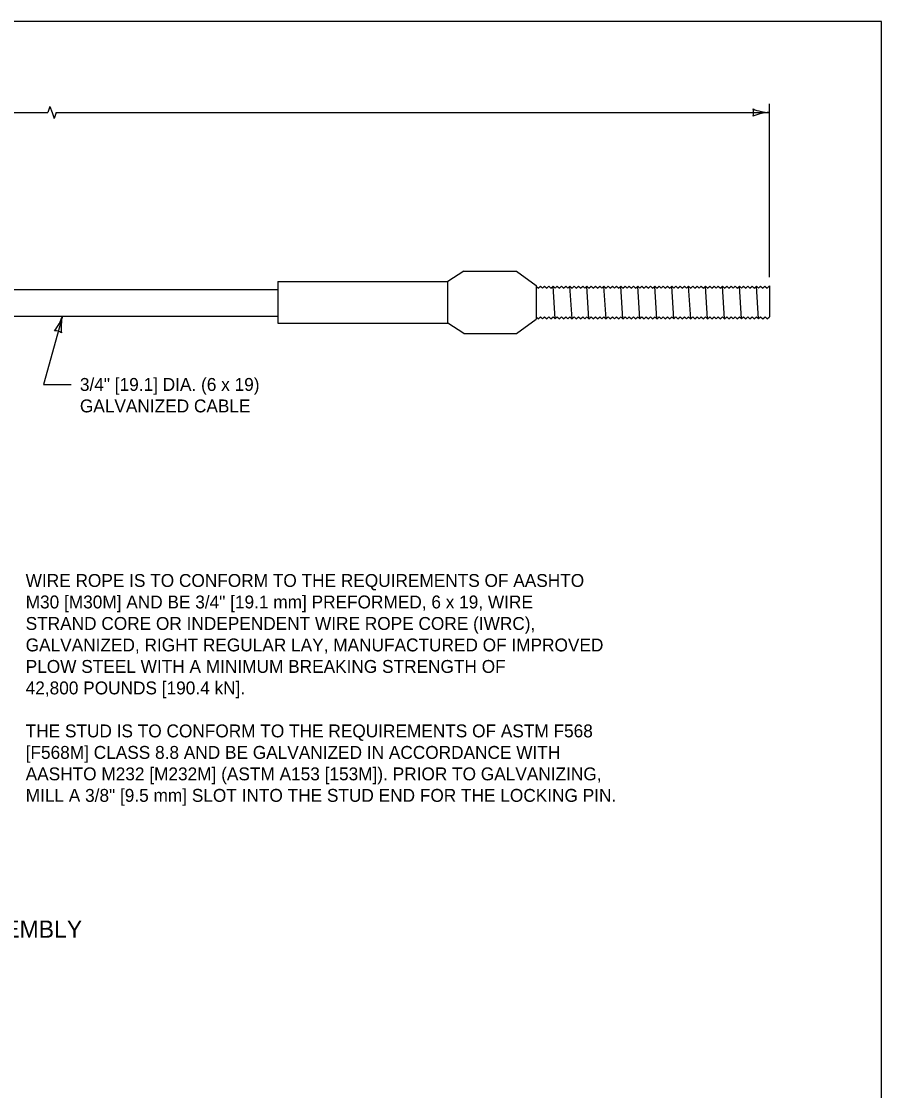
# Model space of a CAD drawing. Extents: x 49991.4 to 50021, y 49987.6 to 50011.4.
# Drawn here: x 50004.612 to 50008.615, y 50006.287 to 50011.263 of the extents above; entities that cross this region are included whole.
import ezdxf

# ---------------------------------------------------------------- set-up
doc = ezdxf.new("R2010")
doc.units = 0
for name, color, linetype in [('Level 1', 7, 'Continuous'), ('Level 2', 7, 'Continuous'), ('Level 3', 7, 'Continuous')]:
    doc.layers.add(name, color=color, linetype=linetype)

msp = doc.modelspace()

# ---------------------------------------------------------------- linework, layer by layer
at = {"layer": 'Level 1'}
for p, q in [((50006.6708, 50010.1011), (50006.5956, 50010.0531)), ((50006.6708, 50010.1011), (50006.9152, 50010.1011)), ((50006.9152, 50010.1011), (50007.007, 50010.0335)), ((50005.8048, 50010.0531), (50005.8048, 50009.8577)), ((50005.8048, 50010.0531), (50006.5956, 50010.0531)), ((50006.5956, 50009.8577), (50006.5956, 50010.0531)), ((50004.5624, 50010.0157), (50005.8048, 50010.0157)), ((50007.007, 50010.0335), (50007.007, 50009.8771)), ((50007.007, 50010.0311), (50007.017, 50010.0213)), ((50007.017, 50010.0213), (50007.0268, 50010.0311)), ((50007.0268, 50010.0311), (50007.0366, 50010.0213)), ((50007.0366, 50010.0213), (50007.0464, 50010.0311)), ((50007.0464, 50010.0311), (50007.0564, 50010.0213)), ((50007.0564, 50010.0213), (50007.0662, 50010.0311)), ((50007.0662, 50010.0311), (50007.076, 50010.0213)), ((50007.076, 50010.0213), (50007.0858, 50010.0311)), ((50007.0858, 50010.0311), (50007.0958, 50010.0213)), ((50007.0958, 50009.8785), (50007.0858, 50010.0311)), ((50007.0958, 50010.0213), (50007.1056, 50010.0311)), ((50007.1056, 50010.0311), (50007.1154, 50010.0213)), ((50007.1154, 50010.0213), (50007.1252, 50010.0311)), ((50007.1252, 50010.0311), (50007.135, 50010.0213)), ((50007.135, 50010.0213), (50007.145, 50010.0311)), ((50007.145, 50010.0311), (50007.1546, 50010.0213)), ((50007.1546, 50010.0213), (50007.1646, 50010.0311)), ((50007.1646, 50010.0311), (50007.1744, 50010.0213)), ((50007.1744, 50009.8785), (50007.1646, 50010.0311)), ((50007.1744, 50010.0213), (50007.1844, 50010.0311)), ((50007.1844, 50010.0311), (50007.194, 50010.0213)), ((50007.194, 50010.0213), (50007.2038, 50010.0311)), ((50007.2038, 50010.0311), (50007.2138, 50010.0213)), ((50007.2138, 50010.0213), (50007.2238, 50010.0311)), ((50007.2238, 50010.0311), (50007.2334, 50010.0213)), ((50007.2334, 50010.0213), (50007.2434, 50010.0311)), ((50007.2434, 50010.0311), (50007.253, 50010.0213)), ((50007.253, 50009.8785), (50007.2434, 50010.0311)), ((50007.253, 50010.0213), (50007.263, 50010.0311)), ((50007.263, 50010.0311), (50007.2732, 50010.0213)), ((50007.2732, 50010.0213), (50007.283, 50010.0311)), ((50007.283, 50010.0311), (50007.2928, 50010.0213)), ((50007.2928, 50010.0213), (50007.3028, 50010.0311)), ((50007.3028, 50010.0311), (50007.3126, 50010.0213)), ((50007.3126, 50010.0213), (50007.3224, 50010.0311)), ((50007.3224, 50010.0311), (50007.3322, 50010.0213)), ((50007.3322, 50009.8785), (50007.3224, 50010.0311)), ((50007.3322, 50010.0213), (50007.342, 50010.0311)), ((50007.342, 50010.0311), (50007.352, 50010.0213)), ((50007.352, 50010.0213), (50007.3618, 50010.0311)), ((50007.3618, 50010.0311), (50007.3716, 50010.0213)), ((50007.3716, 50010.0213), (50007.3814, 50010.0311)), ((50007.3814, 50010.0311), (50007.3914, 50010.0213)), ((50007.3914, 50010.0213), (50007.4012, 50010.0311)), ((50007.4012, 50010.0311), (50007.4108, 50010.0213)), ((50007.4108, 50009.8785), (50007.4012, 50010.0311)), ((50007.4108, 50010.0213), (50007.4208, 50010.0311)), ((50007.4208, 50010.0311), (50007.4308, 50010.0213)), ((50007.4308, 50010.0213), (50007.4406, 50010.0311)), ((50007.4406, 50010.0311), (50007.4504, 50010.0213)), ((50007.4504, 50010.0213), (50007.46, 50010.0311)), ((50007.46, 50010.0311), (50007.47, 50010.0213)), ((50007.47, 50010.0213), (50007.48, 50010.0311)), ((50007.48, 50010.0311), (50007.4896, 50010.0213)), ((50007.4896, 50009.8785), (50007.48, 50010.0311)), ((50007.4896, 50010.0213), (50007.4996, 50010.0311)), ((50007.4996, 50010.0311), (50007.5094, 50010.0213)), ((50007.5094, 50010.0213), (50007.5194, 50010.0311)), ((50007.5194, 50010.0311), (50007.5294, 50010.0213)), ((50007.5294, 50010.0213), (50007.5394, 50010.0311)), ((50007.5394, 50010.0311), (50007.549, 50010.0213)), ((50007.549, 50010.0213), (50007.559, 50010.0311)), ((50007.559, 50010.0311), (50007.5688, 50010.0213)), ((50007.5688, 50009.8785), (50007.559, 50010.0311)), ((50007.5688, 50010.0213), (50007.5788, 50010.0311)), ((50007.5788, 50010.0311), (50007.5884, 50010.0213)), ((50007.5884, 50010.0213), (50007.5984, 50010.0311)), ((50007.5984, 50010.0311), (50007.6082, 50010.0213)), ((50007.6082, 50010.0213), (50007.618, 50010.0311)), ((50007.618, 50010.0311), (50007.6278, 50010.0213)), ((50007.6278, 50010.0213), (50007.6378, 50010.0311)), ((50007.6378, 50010.0311), (50007.6476, 50010.0213)), ((50007.6476, 50009.8785), (50007.6378, 50010.0311)), ((50007.6476, 50010.0213), (50007.6574, 50010.0311)), ((50007.6574, 50010.0311), (50007.667, 50010.0213)), ((50007.667, 50010.0213), (50007.677, 50010.0311)), ((50007.677, 50010.0311), (50007.687, 50010.0213)), ((50007.687, 50010.0213), (50007.6968, 50010.0311)), ((50007.6968, 50010.0311), (50007.7066, 50010.0213)), ((50007.7066, 50010.0213), (50007.7164, 50010.0311)), ((50007.7164, 50010.0311), (50007.7264, 50010.0213)), ((50007.7264, 50009.8785), (50007.7164, 50010.0311)), ((50007.7264, 50010.0213), (50007.7362, 50010.0311)), ((50007.7362, 50010.0311), (50007.7458, 50010.0213)), ((50007.7458, 50010.0213), (50007.7558, 50010.0311)), ((50007.7558, 50010.0311), (50007.7656, 50010.0213)), ((50007.7656, 50010.0213), (50007.7756, 50010.0311)), ((50007.7756, 50010.0311), (50007.7858, 50010.0213)), ((50007.7858, 50010.0213), (50007.7956, 50010.0311)), ((50007.7956, 50010.0311), (50007.8052, 50010.0213)), ((50007.8052, 50009.8785), (50007.7956, 50010.0311)), ((50007.8052, 50010.0213), (50007.8152, 50010.0311)), ((50007.8152, 50010.0311), (50007.825, 50010.0213)), ((50007.825, 50010.0213), (50007.835, 50010.0311)), ((50007.835, 50010.0311), (50007.8448, 50010.0213)), ((50007.8448, 50010.0213), (50007.8546, 50010.0311)), ((50007.8546, 50010.0311), (50007.8644, 50010.0213)), ((50007.8644, 50010.0213), (50007.8744, 50010.0311)), ((50007.8744, 50010.0311), (50007.884, 50010.0213)), ((50007.884, 50009.8785), (50007.8744, 50010.0311)), ((50007.884, 50010.0213), (50007.894, 50010.0311)), ((50007.894, 50010.0311), (50007.9038, 50010.0213)), ((50007.9038, 50010.0213), (50007.9138, 50010.0311)), ((50007.9138, 50010.0311), (50007.9234, 50010.0213)), ((50007.9234, 50010.0213), (50007.9334, 50010.0311)), ((50007.9334, 50010.0311), (50007.9432, 50010.0213)), ((50007.9432, 50010.0213), (50007.953, 50010.0311)), ((50007.953, 50010.0311), (50007.9628, 50010.0213)), ((50007.9628, 50009.8785), (50007.953, 50010.0311)), ((50007.9628, 50010.0213), (50007.9726, 50010.0311)), ((50007.9726, 50010.0311), (50007.9826, 50010.0213)), ((50007.9826, 50010.0213), (50007.9924, 50010.0311)), ((50007.9924, 50010.0311), (50008.002, 50010.0213)), ((50008.002, 50010.0213), (50008.012, 50010.0311)), ((50008.012, 50010.0311), (50008.0218, 50010.0213)), ((50008.0218, 50010.0213), (50008.0318, 50010.0311)), ((50008.0318, 50010.0311), (50008.042, 50010.0213)), ((50008.042, 50009.8785), (50008.0318, 50010.0311)), ((50008.042, 50010.0213), (50008.0518, 50010.0311)), ((50008.0518, 50010.0311), (50008.0614, 50010.0213)), ((50008.0614, 50010.0213), (50008.0714, 50010.0311)), ((50008.0714, 50010.0311), (50008.0814, 50010.0213)), ((50008.0814, 50010.0213), (50008.0922, 50010.0321)), ((50008.0922, 50010.0321), (50008.0922, 50009.8879)), ((50004.5692, 50009.8915), (50005.8048, 50009.8915)), ((50007.007, 50009.8883), (50007.017, 50009.8785)), ((50007.017, 50009.8785), (50007.0268, 50009.8883)), ((50007.0268, 50009.8883), (50007.0366, 50009.8785)), ((50007.0366, 50009.8785), (50007.0464, 50009.8883)), ((50007.0464, 50009.8883), (50007.0564, 50009.8785)), ((50007.0564, 50009.8785), (50007.0662, 50009.8883)), ((50007.0662, 50009.8883), (50007.076, 50009.8785)), ((50007.076, 50009.8785), (50007.0858, 50009.8883)), ((50007.0858, 50009.8883), (50007.0958, 50009.8785)), ((50007.0958, 50009.8785), (50007.1056, 50009.8883)), ((50007.1056, 50009.8883), (50007.1154, 50009.8785)), ((50007.1154, 50009.8785), (50007.1252, 50009.8883)), ((50007.1252, 50009.8883), (50007.135, 50009.8785)), ((50007.135, 50009.8785), (50007.145, 50009.8883)), ((50007.145, 50009.8883), (50007.1546, 50009.8785)), ((50007.1546, 50009.8785), (50007.1646, 50009.8883)), ((50007.1646, 50009.8883), (50007.1744, 50009.8785)), ((50007.1744, 50009.8785), (50007.1844, 50009.8883)), ((50007.1844, 50009.8883), (50007.194, 50009.8785)), ((50007.194, 50009.8785), (50007.2038, 50009.8883)), ((50007.2038, 50009.8883), (50007.2138, 50009.8785)), ((50007.2138, 50009.8785), (50007.2238, 50009.8883)), ((50007.2238, 50009.8883), (50007.2334, 50009.8785)), ((50007.2334, 50009.8785), (50007.2434, 50009.8883)), ((50007.2434, 50009.8883), (50007.253, 50009.8785)), ((50007.253, 50009.8785), (50007.263, 50009.8883)), ((50007.263, 50009.8883), (50007.2732, 50009.8785)), ((50007.2732, 50009.8785), (50007.283, 50009.8883)), ((50007.283, 50009.8883), (50007.2928, 50009.8785)), ((50007.2928, 50009.8785), (50007.3028, 50009.8883)), ((50007.3028, 50009.8883), (50007.3126, 50009.8785)), ((50007.3126, 50009.8785), (50007.3224, 50009.8883)), ((50007.3224, 50009.8883), (50007.3322, 50009.8785)), ((50007.3322, 50009.8785), (50007.342, 50009.8883)), ((50007.342, 50009.8883), (50007.352, 50009.8785)), ((50007.352, 50009.8785), (50007.3618, 50009.8883)), ((50007.3618, 50009.8883), (50007.3716, 50009.8785)), ((50007.3716, 50009.8785), (50007.3814, 50009.8883)), ((50007.3814, 50009.8883), (50007.3914, 50009.8785)), ((50007.3914, 50009.8785), (50007.4012, 50009.8883)), ((50007.4012, 50009.8883), (50007.4108, 50009.8785)), ((50007.4108, 50009.8785), (50007.4208, 50009.8883)), ((50007.4208, 50009.8883), (50007.4308, 50009.8785)), ((50007.4308, 50009.8785), (50007.4406, 50009.8883)), ((50007.4406, 50009.8883), (50007.4504, 50009.8785)), ((50007.4504, 50009.8785), (50007.46, 50009.8883)), ((50007.46, 50009.8883), (50007.47, 50009.8785)), ((50007.47, 50009.8785), (50007.48, 50009.8883)), ((50007.48, 50009.8883), (50007.4896, 50009.8785)), ((50007.4896, 50009.8785), (50007.4996, 50009.8883)), ((50007.4996, 50009.8883), (50007.5094, 50009.8785)), ((50007.5094, 50009.8785), (50007.5194, 50009.8883)), ((50007.5194, 50009.8883), (50007.5294, 50009.8785)), ((50007.5294, 50009.8785), (50007.5394, 50009.8883)), ((50007.5394, 50009.8883), (50007.549, 50009.8785)), ((50007.549, 50009.8785), (50007.559, 50009.8883)), ((50007.559, 50009.8883), (50007.5688, 50009.8785)), ((50007.5688, 50009.8785), (50007.5788, 50009.8883)), ((50007.5788, 50009.8883), (50007.5884, 50009.8785)), ((50007.5884, 50009.8785), (50007.5984, 50009.8883)), ((50007.5984, 50009.8883), (50007.6082, 50009.8785)), ((50007.6082, 50009.8785), (50007.618, 50009.8883)), ((50007.618, 50009.8883), (50007.6278, 50009.8785)), ((50007.6278, 50009.8785), (50007.6378, 50009.8883)), ((50007.6378, 50009.8883), (50007.6476, 50009.8785)), ((50007.6476, 50009.8785), (50007.6574, 50009.8883)), ((50007.6574, 50009.8883), (50007.667, 50009.8785)), ((50007.667, 50009.8785), (50007.677, 50009.8883)), ((50007.677, 50009.8883), (50007.687, 50009.8785)), ((50007.687, 50009.8785), (50007.6968, 50009.8883)), ((50007.6968, 50009.8883), (50007.7066, 50009.8785)), ((50007.7066, 50009.8785), (50007.7164, 50009.8883)), ((50007.7164, 50009.8883), (50007.7264, 50009.8785)), ((50007.7264, 50009.8785), (50007.7362, 50009.8883)), ((50007.7362, 50009.8883), (50007.7458, 50009.8785)), ((50007.7458, 50009.8785), (50007.7558, 50009.8883)), ((50007.7558, 50009.8883), (50007.7656, 50009.8785)), ((50007.7656, 50009.8785), (50007.7756, 50009.8883)), ((50007.7756, 50009.8883), (50007.7858, 50009.8785)), ((50007.7858, 50009.8785), (50007.7956, 50009.8883)), ((50007.7956, 50009.8883), (50007.8052, 50009.8785)), ((50007.8052, 50009.8785), (50007.8152, 50009.8883)), ((50007.8152, 50009.8883), (50007.825, 50009.8785)), ((50007.825, 50009.8785), (50007.835, 50009.8883)), ((50007.835, 50009.8883), (50007.8448, 50009.8785)), ((50007.8448, 50009.8785), (50007.8546, 50009.8883)), ((50007.8546, 50009.8883), (50007.8644, 50009.8785)), ((50007.8644, 50009.8785), (50007.8744, 50009.8883)), ((50007.8744, 50009.8883), (50007.884, 50009.8785)), ((50007.884, 50009.8785), (50007.894, 50009.8883)), ((50007.894, 50009.8883), (50007.9038, 50009.8785)), ((50007.9038, 50009.8785), (50007.9138, 50009.8883)), ((50007.9138, 50009.8883), (50007.9234, 50009.8785)), ((50007.9234, 50009.8785), (50007.9334, 50009.8883)), ((50007.9334, 50009.8883), (50007.9432, 50009.8785)), ((50007.9432, 50009.8785), (50007.953, 50009.8883)), ((50007.953, 50009.8883), (50007.9628, 50009.8785)), ((50007.9628, 50009.8785), (50007.9726, 50009.8883)), ((50007.9726, 50009.8883), (50007.9826, 50009.8785)), ((50007.9826, 50009.8785), (50007.9924, 50009.8883)), ((50007.9924, 50009.8883), (50008.002, 50009.8785)), ((50008.002, 50009.8785), (50008.012, 50009.8883)), ((50008.012, 50009.8883), (50008.0218, 50009.8785)), ((50008.0218, 50009.8785), (50008.0318, 50009.8883)), ((50008.0318, 50009.8883), (50008.042, 50009.8785)), ((50008.042, 50009.8785), (50008.0518, 50009.8883)), ((50008.0518, 50009.8883), (50008.0617, 50009.8782)), ((50008.0617, 50009.8782), (50008.0721, 50009.8884)), ((50008.0721, 50009.8884), (50008.0822, 50009.8785)), ((50008.0822, 50009.8785), (50008.0922, 50009.8879)), ((50005.8048, 50009.8577), (50006.5956, 50009.8577)), ((50006.6708, 50009.8097), (50006.5956, 50009.8577)), ((50006.9152, 50009.8097), (50007.007, 50009.8771)), ((50006.6708, 50009.8097), (50006.9152, 50009.8097))]:
    msp.add_line(p, q, dxfattribs=at)
msp.add_lwpolyline([(50008.6146, 50011.2628), (50000.3356, 50011.2628), (50000.3356, 50000.0624), (50008.6146, 50000.0624)], close=True, dxfattribs=at)
at = {"layer": 'Level 3'}
for p, q in [((50000.8546, 50010.8387), (50004.735, 50010.8387)), ((50004.7448, 50010.8661), (50004.735, 50010.8387)), ((50004.7448, 50010.8661), (50004.7544, 50010.8387)), ((50004.7544, 50010.8387), (50004.7642, 50010.8113)), ((50004.7738, 50010.8387), (50004.7642, 50010.8113)), ((50004.7738, 50010.8387), (50008.0922, 50010.8387)), ((50008.0922, 50010.0721), (50008.0922, 50010.8787)), ((50004.8025, 50009.8915), (50004.7146, 50009.5733)), ((50004.7146, 50009.5733), (50004.8442, 50009.5733))]:
    msp.add_line(p, q, dxfattribs=at)
for centre, radius, start, end in [((50008.1014, 50011.0608), 0.2223, 247.456, 267.6395), ((50007.964, 50010.8387), 0.0548, 342.1388, 17.8612), ((50008.1037, 50010.606), 0.233, 92.8273, 112.0772), ((50004.5908, 50009.9594), 0.2223, 322.0279, 342.2114), ((50005.0299, 50009.8407), 0.233, 167.3992, 186.649), ((50004.7684, 50009.7679), 0.0548, 56.7107, 92.4331)]:
    msp.add_arc(centre, radius, start, end, dxfattribs=at)

# ---------------------------------------------------------------- texts
at = {"layer": 'Level 2'}
for s, height, p in [('3/4" [19.1] DIA. (6 x 19)', 0.06, (50004.8842, 50009.5433)), ('GALVANIZED CABLE', 0.06, (50004.8842, 50009.4433)), ('WIRE ROPE IS TO CONFORM TO THE REQUIREMENTS OF AASHTO', 0.06, (50004.6318, 50008.631)), ('M30 [M30M] AND BE 3/4" [19.1 mm] PREFORMED, 6 x 19, WIRE ', 0.06, (50004.6318, 50008.531)), ('STRAND CORE OR INDEPENDENT WIRE ROPE CORE (IWRC), ', 0.06, (50004.6318, 50008.431)), ('GALVANIZED, RIGHT REGULAR LAY, MANUFACTURED OF IMPROVED ', 0.06, (50004.6318, 50008.331)), ('PLOW STEEL WITH A MINIMUM BREAKING STRENGTH OF', 0.06, (50004.6318, 50008.231)), ('42,800 POUNDS [190.4 kN].', 0.06, (50004.6318, 50008.131)), ('THE STUD IS TO CONFORM TO THE REQUIREMENTS OF ASTM F568 ', 0.06, (50004.6318, 50007.931)), ('[F568M] CLASS 8.8 AND BE GALVANIZED IN ACCORDANCE WITH ', 0.06, (50004.6318, 50007.831)), ('AASHTO M232 [M232M] (ASTM A153 [153M]). PRIOR TO GALVANIZING, ', 0.06, (50004.6318, 50007.731)), ('MILL A 3/8" [9.5 mm] SLOT INTO THE STUD END FOR THE LOCKING PIN.', 0.06, (50004.6318, 50007.631)), ('CABLE ASSEMBLY', 0.08, (50003.9374, 50006.9986))]:
    msp.add_text(s, height=height, dxfattribs=at).set_placement(p)

doc.saveas('drawing.dxf')
